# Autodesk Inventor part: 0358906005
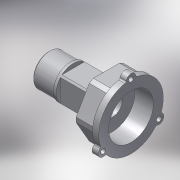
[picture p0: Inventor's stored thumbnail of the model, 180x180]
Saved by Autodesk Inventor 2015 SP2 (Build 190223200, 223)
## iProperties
Created: 2017-01
Part Number: 0358906005
Material: PVC-Piping
Description: PLASSON MALE BSPT WITH FREE NUT 1/2"-3/4"
Document SubType Name: Modeling
Designer: KIM
Mass: 43.954 g
Surface Area: 139.205 cm^2
Volume: 31.3957 cm^3
Density: 1.4 g/cm^3
Appearance: Smooth - White
Author: KIM
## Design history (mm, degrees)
derived "03589.ipt"
feature "Solid1::03589.ipt"
tag "TaggingFeature1"
body "Solid1"
other parameters: "d0" = 56, "d1" = 24.117, "d2" = 20.955, "d4" = 22.00275, "d6" = 16.8, "d7" = 4.2, "d8" = 39.2, "d9" = 4.2, "d10" = 12.573, "d13" = 1, "d14" = 2, "d15" = 8.5, "d17" = 0, "d19" = 360 deg, "d21" = 5.23875, "d22" = 45 deg, "d30" = 0, "d31" = 2, "d34" = 6.2865, "d36" = 0, "d37" = 3.14325, "d39" = 0, "d41" = 360 deg, "d43" = 1.04775, "d44" = 0.62865, "d47" = 16, "G_" = 24.117, "G_1" = 20.955, "H_" = 56, "l_2" = 16
